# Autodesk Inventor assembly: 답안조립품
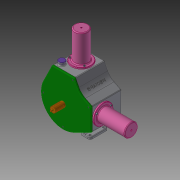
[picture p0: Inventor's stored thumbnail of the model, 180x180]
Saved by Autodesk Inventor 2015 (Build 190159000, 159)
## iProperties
Created: 2022-01
Part Number: 답안조립품
Document SubType Name: Assembly
Designer: user
Author: user
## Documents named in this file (13)
- C:\Users\user\Desktop\620117V1006\답안조립품.iam
- C:\Users\user\Desktop\620117V1006\너트 M3.ipt
- C:\Users\user\Desktop\620117V1006\베어링 20 x 37 x 9.ipt
- C:\Users\user\Desktop\620117V1006\본체.ipt
- C:\Users\user\Desktop\620117V1006\볼트 M3 x 12.ipt
- C:\Users\user\Desktop\620117V1006\실린더.ipt
- C:\Users\user\Desktop\620117V1006\앞커버.ipt
- C:\Users\user\Desktop\620117V1006\축.ipt
- C:\Users\user\Desktop\620117V1006\측정게이지.ipt
- C:\Users\user\Desktop\620117V1006\커넥팅로드 캡.ipt
- C:\Users\user\Desktop\620117V1006\커넥팅로드.ipt
- C:\Users\user\Desktop\620117V1006\피스톤 핀.ipt
- C:\Users\user\Desktop\620117V1006\피스톤.ipt
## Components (4 placed, 2 different names)
1. 피스톤 핀:1
2. 피스톤:1
3. 피스톤:2
4. 피스톤 핀:2
